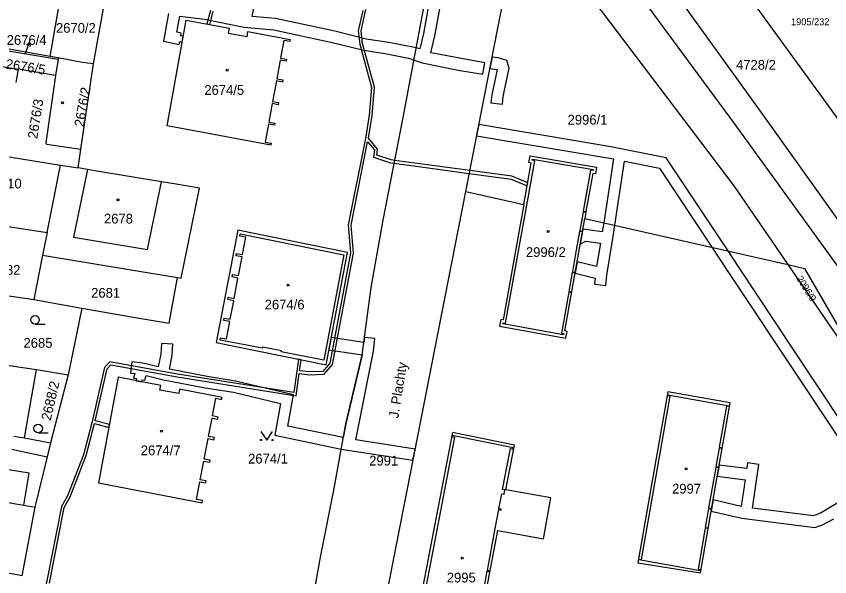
# Model space of a CAD drawing. Extents: x -756746 to -753363, y -1166406 to -1161727.
# Drawn here: x -755238.8 to -755096.9, y -1165184.7 to -1165086.9 of the extents above; entities that cross this region are included whole.
import ezdxf

# ---------------------------------------------------------------- set-up
doc = ezdxf.new("R2010")
doc.units = 0
for name, color, linetype in [('Hranice parcel', 7, 'Continuous'), ('Parcelní čísla', 7, 'Continuous'), ('Pop  PČ popisy', 7, 'Continuous'), ('Poz předměty', 7, 'Continuous'), ('Vnitřní kresba', 7, 'Continuous'), ('Věcná břemena k části', 7, 'Continuous'), ('Značky budov', 7, 'Continuous'), ('Značky kultur', 7, 'Continuous')]:
    doc.layers.add(name, color=color, linetype=linetype)

msp = doc.modelspace()

# ---------------------------------------------------------------- linework, layer by layer
at = {"layer": 'Hranice parcel'}
for p, q in [((-755160.42, -1165117.49), (-755150.8, -1165068.69)), ((-755225.33, -1165095.26), (-755222.94, -1165081.86)), ((-755232.91, -1165093.94), (-755242.08, -1165092.35)), ((-755241.62, -1165092.72), (-755231.52, -1165094.42)), ((-755231.49, -1165094.19), (-755232.91, -1165093.94)), ((-755231.49, -1165094.19), (-755231.52, -1165094.42)), ((-755242.1, -1165095.57), (-755238.48, -1165096.18)), ((-755231.52, -1165094.42), (-755231.95, -1165097.29)), ((-755227.53, -1165110.13), (-755225.33, -1165095.26)), ((-755238.48, -1165096.18), (-755238.88, -1165098.48)), ((-755231.95, -1165097.29), (-755238.48, -1165096.18)), ((-755228.02, -1165113.41), (-755227.53, -1165110.13)), ((-755233.44, -1165124.65), (-755231.1, -1165112.95)), ((-755231.1, -1165112.95), (-755228.02, -1165113.41)), ((-755179.62, -1165215.45), (-755160.42, -1165117.49)), ((-755160.42, -1165117.49), (-755150.27, -1165119.8)), ((-755139.46, -1165121.18), (-755139.65, -1165122.21)), ((-755140.68, -1165128.11), (-755139.65, -1165122.21)), ((-755139.65, -1165122.21), (-755104.24, -1165130.26)), ((-755246.05, -1165122.75), (-755233.44, -1165124.65)), ((-755233.44, -1165124.65), (-755234.22, -1165128.61)), ((-755234.22, -1165128.61), (-755235.77, -1165136.38)), ((-755234.22, -1165128.61), (-755210.71, -1165132.55)), ((-755104.24, -1165130.26), (-755087.72, -1165154.39)), ((-755242.45, -1165135.36), (-755235.77, -1165136.38)), ((-755227.37, -1165137.87), (-755229.77, -1165149.51)), ((-755242.09, -1165147.57), (-755235.29, -1165148.57)), ((-755237.41, -1165160.49), (-755235.29, -1165148.57)), ((-755235.29, -1165148.57), (-755229.77, -1165149.51)), ((-755229.77, -1165149.51), (-755232.82, -1165161.37)), ((-755239.26, -1165160.22), (-755237.41, -1165160.49)), ((-755237.41, -1165160.49), (-755232.82, -1165161.37)), ((-755237.49, -1165172.27), (-755235.61, -1165172.6))]:
    msp.add_line(p, q, dxfattribs=at)
for points in [[(-755195.18, -1165232.73), (-755194.72, -1165230.22), (-755190.08, -1165204.4), (-755187.88, -1165193.31), (-755185.72, -1165181.35), (-755183.4, -1165169.62), (-755181.35, -1165158.07), (-755178.5, -1165145.99), (-755176.9, -1165134.25), (-755174.82, -1165122.5), (-755171.34, -1165104.62), (-755169.11, -1165092.87), (-755166.91, -1165081.07), (-755164.91, -1165069.54), (-755163.98, -1165065.31), (-755179.46, -1165046.33)], [(-755128.64, -1165061.22), (-755109.28, -1165085.91), (-755070.16, -1165139.75), (-755029.65, -1165203.95), (-755020.68, -1165217.39)], [(-755143.12, -1165077.96), (-755139.65, -1165082.14), (-755113.63, -1165116.54), (-755104.24, -1165130.26)], [(-755071.5, -1165165.83), (-755094.76, -1165131.6), (-755113.5, -1165105.68), (-755130.36, -1165082.71), (-755132.91, -1165079.45)], [(-755232.91, -1165093.94), (-755230.59, -1165080.61), (-755222.94, -1165081.86)], [(-755191.09, -1165091.34), (-755192.15, -1165091.15), (-755192.71, -1165094.24), (-755191.66, -1165094.43), (-755191.73, -1165094.8), (-755192.79, -1165094.61), (-755193.37, -1165097.85), (-755192.33, -1165098.04), (-755192.39, -1165098.41), (-755193.45, -1165098.22), (-755194.1, -1165101.8), (-755193.06, -1165101.99), (-755193.12, -1165102.37), (-755194.18, -1165102.17), (-755194.77, -1165105.41), (-755193.72, -1165105.61), (-755193.78, -1165105.97), (-755194.83, -1165105.77), (-755195.41, -1165108.88), (-755194.35, -1165109.08), (-755194.43, -1165109.43), (-755212.52, -1165106.05), (-755209.2, -1165087.6), (-755201.69, -1165088.99), (-755201.86, -1165089.88), (-755198.56, -1165090.49), (-755198.4, -1165089.6), (-755191.02, -1165090.97), (-755191.09, -1165091.34)], [(-755225.33, -1165095.26), (-755227.34, -1165094.98), (-755231.49, -1165094.19)], [(-755231.95, -1165097.29), (-755233.69, -1165109), (-755233.54, -1165109.24), (-755227.53, -1165110.13)], [(-755249.11, -1165110.01), (-755248.72, -1165110.07), (-755231.1, -1165112.95)], [(-755150.27, -1165119.8), (-755148.97, -1165112.55), (-755149.4, -1165112.47), (-755149.19, -1165111.3), (-755137.58, -1165113.28)], [(-755210.71, -1165132.55), (-755210.08, -1165132.66), (-755206.88, -1165116.94), (-755210.94, -1165116.24), (-755213.46, -1165115.83), (-755224.74, -1165113.97), (-755226.41, -1165113.7), (-755228.02, -1165113.41)], [(-755137.58, -1165113.28), (-755137.79, -1165114.45), (-755138.22, -1165114.37), (-755139.43, -1165121.02), (-755139.46, -1165121.18)], [(-755150.27, -1165119.8), (-755151.42, -1165126.23), (-755153.87, -1165139.91), (-755154.3, -1165139.83), (-755154.52, -1165141), (-755142.92, -1165143.09)], [(-755200.17, -1165124.26), (-755203.92, -1165143.88), (-755184.78, -1165147.76), (-755181.05, -1165128.16), (-755200.17, -1165124.26)], [(-755142.92, -1165143.09), (-755142.71, -1165141.92), (-755143.14, -1165141.84), (-755140.68, -1165128.11)], [(-755104.24, -1165130.26), (-755101.31, -1165130.93), (-755087.72, -1165154.39)], [(-755227.37, -1165137.87), (-755218.06, -1165139.49), (-755212.14, -1165140.47), (-755210.71, -1165132.55)], [(-755235.77, -1165136.38), (-755230.93, -1165137.25), (-755227.37, -1165137.87)], [(-755207.36, -1165171.26), (-755206.78, -1165168.17), (-755205.74, -1165168.37), (-755205.68, -1165168), (-755206.71, -1165167.81), (-755206.1, -1165164.58), (-755205.07, -1165164.77), (-755204.99, -1165164.41), (-755206.02, -1165164.21), (-755205.35, -1165160.64), (-755204.33, -1165160.83), (-755204.25, -1165160.46), (-755205.28, -1165160.27), (-755204.67, -1165157.04), (-755203.64, -1165157.24), (-755203.57, -1165156.87), (-755204.59, -1165156.68), (-755204.02, -1165153.6), (-755202.99, -1165153.79), (-755202.92, -1165153.45), (-755210.33, -1165152.01), (-755210.48, -1165152.79), (-755213.77, -1165152.16), (-755213.62, -1165151.37), (-755221.03, -1165149.94), (-755224.5, -1165168.35), (-755206.4, -1165171.82), (-755206.33, -1165171.45), (-755207.36, -1165171.26)], [(-755125.15, -1165152.46), (-755127.78, -1165167.38), (-755130.41, -1165182.34), (-755119.46, -1165184.03), (-755116.89, -1165169.3), (-755114.29, -1165154.4), (-755125.15, -1165152.46)], [(-755160.8, -1165208.04), (-755159.55, -1165201.4), (-755151.54, -1165202.7), (-755150.29, -1165195.89), (-755158.19, -1165194.35), (-755154.79, -1165176.66), (-755146.86, -1165178.15), (-755145.57, -1165170.99), (-755153.44, -1165169.6), (-755151.91, -1165161.77), (-755162.74, -1165159.58), (-755165.57, -1165174.33), (-755169.05, -1165192.5), (-755171.87, -1165207.15), (-755165.18, -1165208.46)], [(-755232.82, -1165161.37), (-755233.42, -1165163.8), (-755235.61, -1165172.6)], [(-755255.14, -1165169.18), (-755251.05, -1165169.95), (-755248.2, -1165170.48), (-755242.64, -1165171.4), (-755241.26, -1165171.62), (-755237.49, -1165172.27)], [(-755235.61, -1165172.6), (-755237.84, -1165184.59), (-755238.67, -1165184.43)], [(-755238.67, -1165184.43), (-755243.01, -1165183.71), (-755248, -1165183.01), (-755253.35, -1165182.1), (-755259.87, -1165180.99)]]:
    msp.add_lwpolyline(points, dxfattribs=at)
at = {"layer": 'Pop  PČ popisy'}
for p, q in [((-755237.23, -1165093.35), (-755236.51, -1165091.47)), ((-755236.51, -1165091.47), (-755237.06, -1165091.98)), ((-755236.51, -1165091.47), (-755236.44, -1165092.22))]:
    msp.add_line(p, q, dxfattribs=at)
at = {"layer": 'Poz předměty'}
for p, q in [((-755108.7, -1165103.93), (-755146.57, -1165051.26)), ((-755089.86, -1165130.3), (-755108.7, -1165103.93))]:
    msp.add_line(p, q, dxfattribs=at)
at = {"layer": 'Vnitřní kresba'}
for p, q in [((-755149.78, -1165119.91), (-755148.38, -1165112.14)), ((-755148.81, -1165112.06), (-755148.78, -1165111.89)), ((-755148.38, -1165112.14), (-755148.81, -1165112.06)), ((-755148.78, -1165111.89), (-755138.17, -1165113.69)), ((-755226.41, -1165113.7), (-755228.82, -1165125.49)), ((-755138.63, -1165113.78), (-755139.92, -1165120.94)), ((-755138.2, -1165113.86), (-755138.63, -1165113.78)), ((-755138.17, -1165113.69), (-755138.2, -1165113.86)), ((-755215.93, -1165127.65), (-755213.46, -1165115.83)), ((-755150.93, -1165126.32), (-755149.78, -1165119.91)), ((-755139.94, -1165121.09), (-755140.12, -1165122.1)), ((-755139.46, -1165121.18), (-755139.94, -1165121.09)), ((-755139.92, -1165120.94), (-755139.43, -1165121.02)), ((-755140.12, -1165122.1), (-755140.53, -1165124.35)), ((-755228.82, -1165125.49), (-755215.93, -1165127.65)), ((-755199.83, -1165125.29), (-755199.75, -1165124.88)), ((-755198.8, -1165125.49), (-755199.83, -1165125.29)), ((-755199.75, -1165124.88), (-755181.68, -1165128.57)), ((-755199.36, -1165128.52), (-755198.8, -1165125.49)), ((-755140.55, -1165124.5), (-755141.18, -1165128.03)), ((-755140.12, -1165124.57), (-755140.55, -1165124.5)), ((-755140.53, -1165124.35), (-755140.1, -1165124.43)), ((-755140.1, -1165124.43), (-755140.12, -1165124.57)), ((-755153.47, -1165140.5), (-755150.93, -1165126.32)), ((-755200.48, -1165128.74), (-755200.4, -1165128.33)), ((-755200.4, -1165128.33), (-755199.36, -1165128.52)), ((-755141.18, -1165128.03), (-755141.81, -1165131.53)), ((-755199.44, -1165128.93), (-755200.48, -1165128.74)), ((-755200.06, -1165132.19), (-755199.44, -1165128.93)), ((-755181.68, -1165128.57), (-755185.16, -1165146.93)), ((-755201.17, -1165132.41), (-755201.09, -1165131.99)), ((-755200.14, -1165132.61), (-755201.17, -1165132.41)), ((-755201.09, -1165131.99), (-755200.06, -1165132.19)), ((-755141.84, -1165131.67), (-755142.43, -1165134.97)), ((-755141.4, -1165131.74), (-755141.84, -1165131.67)), ((-755141.81, -1165131.53), (-755141.38, -1165131.6)), ((-755141.38, -1165131.6), (-755141.4, -1165131.74)), ((-755200.81, -1165136.16), (-755200.14, -1165132.61)), ((-755142.45, -1165135.1), (-755143.73, -1165142.26)), ((-755142.02, -1165135.18), (-755142.45, -1165135.1)), ((-755142.43, -1165134.97), (-755142, -1165135.05)), ((-755142, -1165135.05), (-755142.02, -1165135.18)), ((-755201.92, -1165136.37), (-755201.84, -1165135.96)), ((-755200.89, -1165136.57), (-755201.92, -1165136.37)), ((-755201.84, -1165135.96), (-755200.81, -1165136.16)), ((-755201.49, -1165139.81), (-755200.89, -1165136.57)), ((-755202.61, -1165140.03), (-755202.53, -1165139.62)), ((-755202.53, -1165139.62), (-755201.49, -1165139.81)), ((-755201.57, -1165140.22), (-755202.61, -1165140.03)), ((-755202.14, -1165143.25), (-755201.57, -1165140.22)), ((-755153.93, -1165140.59), (-755153.89, -1165140.42)), ((-755143.33, -1165142.5), (-755153.93, -1165140.59)), ((-755153.89, -1165140.42), (-755153.47, -1165140.5)), ((-755143.73, -1165142.26), (-755143.3, -1165142.33)), ((-755143.3, -1165142.33), (-755143.33, -1165142.5)), ((-755203.25, -1165143.47), (-755203.18, -1165143.06)), ((-755195.87, -1165144.88), (-755203.25, -1165143.47)), ((-755203.18, -1165143.06), (-755202.14, -1165143.25)), ((-755195.84, -1165144.69), (-755195.87, -1165144.88)), ((-755192.55, -1165145.32), (-755195.84, -1165144.69)), ((-755192.59, -1165145.51), (-755192.55, -1165145.32)), ((-755185.16, -1165146.93), (-755192.59, -1165145.51)), ((-755127.25, -1165167.47), (-755124.75, -1165153.23)), ((-755125.18, -1165153.15), (-755125.15, -1165152.97)), ((-755124.75, -1165153.23), (-755125.18, -1165153.15)), ((-755125.15, -1165152.97), (-755114.47, -1165154.89)), ((-755114.93, -1165154.99), (-755116.18, -1165162.15)), ((-755114.5, -1165155.06), (-755114.93, -1165154.99)), ((-755114.47, -1165154.89), (-755114.5, -1165155.06)), ((-755162.36, -1165160.37), (-755165.06, -1165174.43)), ((-755162.76, -1165160.11), (-755162.79, -1165160.29)), ((-755162.79, -1165160.29), (-755162.36, -1165160.37)), ((-755152.14, -1165162.27), (-755162.76, -1165160.11)), ((-755153.97, -1165169.5), (-755152.62, -1165162.36)), ((-755152.62, -1165162.36), (-755152.17, -1165162.45)), ((-755152.17, -1165162.45), (-755152.14, -1165162.27)), ((-755116.2, -1165162.28), (-755116.77, -1165165.52)), ((-755115.77, -1165162.36), (-755116.2, -1165162.28)), ((-755116.18, -1165162.15), (-755115.75, -1165162.22)), ((-755115.75, -1165162.22), (-755115.77, -1165162.36)), ((-755239.57, -1165162.49), (-755233.42, -1165163.8)), ((-755236.58, -1165166.69), (-755240.2, -1165166.11)), ((-755116.79, -1165165.66), (-755117.41, -1165169.21)), ((-755116.36, -1165165.73), (-755116.79, -1165165.66)), ((-755116.77, -1165165.52), (-755116.34, -1165165.59)), ((-755116.34, -1165165.59), (-755116.36, -1165165.73)), ((-755237.49, -1165172.27), (-755236.58, -1165166.69)), ((-755129.76, -1165181.72), (-755127.25, -1165167.47)), ((-755153.56, -1165169.57), (-755153.97, -1165169.5)), ((-755117.41, -1165169.21), (-755118.03, -1165172.74)), ((-755154.61, -1165172.89), (-755154.11, -1165170.25)), ((-755154.11, -1165170.25), (-755153.7, -1165170.33)), ((-755153.7, -1165170.33), (-755153.56, -1165169.57)), ((-755155.26, -1165176.31), (-755154.63, -1165173.02)), ((-755154.63, -1165173.02), (-755154.22, -1165173.1)), ((-755154.2, -1165172.97), (-755154.61, -1165172.89)), ((-755154.22, -1165173.1), (-755154.2, -1165172.97)), ((-755118.05, -1165172.88), (-755118.62, -1165176.12)), ((-755117.62, -1165172.96), (-755118.05, -1165172.88)), ((-755118.03, -1165172.74), (-755117.6, -1165172.81)), ((-755117.6, -1165172.81), (-755117.62, -1165172.96)), ((-755165.06, -1165174.43), (-755168.54, -1165192.59)), ((-755156.64, -1165183.66), (-755155.26, -1165176.31)), ((-755118.64, -1165176.27), (-755119.89, -1165183.43)), ((-755118.21, -1165176.34), (-755118.64, -1165176.27)), ((-755118.62, -1165176.12), (-755118.18, -1165176.19)), ((-755118.18, -1165176.19), (-755118.21, -1165176.34)), ((-755130.22, -1165181.81), (-755130.19, -1165181.65)), ((-755119.49, -1165183.68), (-755130.22, -1165181.81)), ((-755130.19, -1165181.65), (-755129.76, -1165181.72)), ((-755156.21, -1165183.74), (-755156.64, -1165183.66)), ((-755119.89, -1165183.43), (-755119.46, -1165183.51)), ((-755119.46, -1165183.51), (-755119.49, -1165183.68)), ((-755157.28, -1165187.03), (-755156.67, -1165183.79)), ((-755156.67, -1165183.79), (-755156.24, -1165183.87)), ((-755156.24, -1165183.87), (-755156.21, -1165183.74))]:
    msp.add_line(p, q, dxfattribs=at)
at = {"layer": 'Věcná břemena k části'}
for points in [[(-755166.94, -1165085.41), (-755167.77, -1165089.94), (-755168.4, -1165092.6), (-755169.04, -1165092.47), (-755173.82, -1165091.53), (-755177.78, -1165090.92), (-755183.24, -1165089.55), (-755193.59, -1165087.31), (-755197.66, -1165086.98), (-755194.2, -1165069.63)], [(-755212.24, -1165086.44), (-755213.13, -1165091.29), (-755210.39, -1165091.85), (-755210.3, -1165091.36), (-755209.89, -1165091.44), (-755209.71, -1165090.45), (-755210.12, -1165090.38), (-755210.03, -1165089.89), (-755210.81, -1165089.73), (-755210.3, -1165086.91), (-755205.99, -1165087.45), (-755199.06, -1165088.87), (-755193.89, -1165089.29), (-755183.7, -1165091.49), (-755178.18, -1165092.88), (-755174.16, -1165093.51), (-755170.38, -1165094.25), (-755169.43, -1165094.58), (-755167.99, -1165095.09), (-755161.75, -1165096.33), (-755157.44, -1165097.02), (-755157.09, -1165095.05), (-755166.52, -1165093.34), (-755165.81, -1165090.34), (-755164.48, -1165083.04)], [(-755149.69, -1165116.54), (-755149.59, -1165116.03), (-755152.38, -1165114.86), (-755159.71, -1165113.86), (-755172.79, -1165112.09), (-755173.42, -1165112), (-755175.94, -1165111.2), (-755175.82, -1165110.11), (-755177.4, -1165108.23), (-755176.75, -1165104.25), (-755176.34, -1165099.34), (-755178.42, -1165091.7), (-755178.67, -1165089.51), (-755177.82, -1165085.77)], [(-755178.37, -1165085.93), (-755179.17, -1165089.49), (-755178.91, -1165091.8), (-755176.85, -1165099.39), (-755177.25, -1165104.19), (-755177.91, -1165108.26), (-755180.92, -1165123.36), (-755180.49, -1165128.27), (-755184.13, -1165147.49), (-755185.32, -1165148.91), (-755187.58, -1165149), (-755189.39, -1165148.79), (-755189.12, -1165146.88), (-755189.61, -1165146.78), (-755190.42, -1165152.57), (-755210.7, -1165149.37), (-755222.5, -1165147.21), (-755223.44, -1165148.2)], [(-755204.95, -1165085.94), (-755205.57, -1165088.27), (-755205.08, -1165088.36), (-755204.46, -1165086.05)], [(-755158.12, -1165105.81), (-755158.51, -1165107.78), (-755134.66, -1165111.83), (-755136.34, -1165122.96), (-755136.58, -1165124.56), (-755139.98, -1165124.11), (-755140.44, -1165126.71), (-755139.48, -1165126.19), (-755136.89, -1165126.53), (-755137.58, -1165130.63), (-755140.98, -1165129.79), (-755141.33, -1165131.75), (-755137.85, -1165132.62), (-755137.97, -1165133.7), (-755135.99, -1165133.92), (-755135.79, -1165132.13), (-755134.78, -1165126.08), (-755134.38, -1165123.41), (-755132.69, -1165112.24), (-755126.63, -1165113.44), (-755117.47, -1165127.25), (-755114.43, -1165131.83), (-755101.61, -1165151.15), (-755090.03, -1165168.57), (-755098.5, -1165173.67), (-755099.72, -1165174.11), (-755110.39, -1165172.76), (-755109.28, -1165165.15), (-755111.26, -1165164.86), (-755111.4, -1165165.84), (-755116.18, -1165165.24), (-755116.53, -1165167.21), (-755111.69, -1165167.82), (-755112.36, -1165172.47), (-755117.24, -1165171.33), (-755117.59, -1165173.29), (-755112.27, -1165174.54), (-755099.49, -1165176.15), (-755098.16, -1165175.66), (-755096.19, -1165174.62)], [(-755051.31, -1165235.98), (-755056.2, -1165226.18), (-755068.76, -1165204.62), (-755071.9, -1165199.03), (-755075.13, -1165188.62), (-755087.62, -1165168.58), (-755099.95, -1165150.05), (-755112.77, -1165130.73), (-755114.65, -1165127.89), (-755125.43, -1165111.64), (-755135.1, -1165109.72), (-755158.12, -1165105.81)], [(-755233.03, -1165185.88), (-755230.45, -1165172.68), (-755229.41, -1165170.82), (-755226.62, -1165163.6), (-755225.17, -1165158.01), (-755222.68, -1165158.67), (-755222.58, -1165158.18), (-755225.06, -1165157.53), (-755222.99, -1165148.45), (-755222.32, -1165147.75), (-755210.78, -1165149.86), (-755189.99, -1165153.15), (-755189.46, -1165149.28), (-755187.6, -1165149.51), (-755185.08, -1165149.4), (-755183.66, -1165147.71), (-755179.99, -1165128.3), (-755180.42, -1165123.38), (-755177.52, -1165108.87), (-755176.34, -1165110.27), (-755176.48, -1165111.55), (-755173.53, -1165112.49), (-755172.89, -1165112.58), (-755159.8, -1165114.36), (-755152.51, -1165115.35), (-755149.69, -1165116.54)], [(-755223.44, -1165148.2), (-755225.6, -1165157.65), (-755227.1, -1165163.45), (-755229.86, -1165170.61), (-755230.93, -1165172.5), (-755233.52, -1165185.76), (-755236.33, -1165195.43), (-755237.58, -1165204.98), (-755238.14, -1165208.26), (-755240.89, -1165209.44)]]:
    msp.add_lwpolyline(points, dxfattribs=at)
for points in [[(-755156.19, -1165096.04), (-755154.91, -1165096.21), (-755155.86, -1165100.65), (-755156.01, -1165102.07), (-755154.02, -1165102.28), (-755153.88, -1165100.94), (-755152.83, -1165096), (-755153.26, -1165094.64), (-755154.76, -1165094.22), (-755155.81, -1165094.08)], [(-755213.5, -1165144.06), (-755213.59, -1165145.88), (-755214.06, -1165148.1), (-755216.74, -1165147.45), (-755218.66, -1165147.21), (-755218.92, -1165149.19), (-755218.16, -1165149.29), (-755218.34, -1165150.07), (-755217.85, -1165150.16), (-755217.93, -1165150.54), (-755216.94, -1165150.73), (-755216.87, -1165150.35), (-755216.38, -1165150.45), (-755216.18, -1165149.64), (-755213.12, -1165150.38), (-755205.85, -1165151.8), (-755200.93, -1165152.56), (-755192.73, -1165154.49), (-755193.74, -1165160.06), (-755182.13, -1165162.47), (-755169.62, -1165164.42), (-755169.23, -1165162.46), (-755179.59, -1165160.84), (-755176.51, -1165145.4), (-755176.25, -1165143.19), (-755178.09, -1165142.97), (-755178.21, -1165143.85), (-755183.88, -1165143.01), (-755184.28, -1165145.12), (-755178.5, -1165145.99), (-755181.35, -1165158.07), (-755181.77, -1165160.45), (-755191.42, -1165158.48), (-755190.43, -1165152.97), (-755200.55, -1165150.6), (-755205.51, -1165149.82), (-755212.11, -1165148.54), (-755211.61, -1165146.14), (-755211.51, -1165144.16)]]:
    msp.add_lwpolyline(points, close=True, dxfattribs=at)
at = {"layer": 'Značky budov'}
for centre in [(-755202.03, -1165096.34), (-755230.74, -1165102.02), (-755221.07, -1165118.95), (-755146.03, -1165124.51), (-755191.4, -1165133.85), (-755213.47, -1165159.32), (-755121.97, -1165165.92), (-755161.04, -1165181.5)]:
    msp.add_circle(centre, 0.175, dxfattribs=at)
at = {"layer": 'Značky kultur'}
for p, q in [((-755235.55, -1165140.65), (-755233.8, -1165140.65)), ((-755235.02, -1165159.64), (-755233.27, -1165159.64))]:
    msp.add_line(p, q, dxfattribs=at)
msp.add_lwpolyline([(-755196.13, -1165159.38), (-755195.13, -1165160.88), (-755194.13, -1165159.38)], dxfattribs=at)
for centre, radius in [((-755235.55, -1165139.9), 0.75), ((-755235.02, -1165158.89), 0.75), ((-755196.13, -1165160.88), 0.1), ((-755194.13, -1165160.88), 0.1)]:
    msp.add_circle(centre, radius, dxfattribs=at)

# ---------------------------------------------------------------- texts
at = {"layer": 'Parcelní čísla'}
for s, height, p in [('2670/2', 1.7, (-755231.9, -1165089.82)), ('1905/232', 1.2, (-755103.66, -1165088.5)), ('2676/4', 1.7, (-755240.49, -1165091.93)), ('4728/2', 1.7, (-755113.26, -1165096.26)), ('2674/5', 1.7, (-755206.02, -1165100.65)), ('2996/1', 1.7, (-755142.64, -1165105.84)), ('2676/10', 1.7, (-755246.09, -1165116.98)), ('2678', 1.7, (-755223.52, -1165123.1)), ('2996/2', 1.7, (-755149.91, -1165128.94)), ('2682', 1.7, (-755243.15, -1165132.05)), ('2681', 1.7, (-755225.76, -1165136.05)), ('2674/6', 1.7, (-755195.48, -1165138.09)), ('2685', 1.7, (-755237.56, -1165144.78)), ('2674/7', 1.7, (-755217.1, -1165163.53)), ('2674/1', 1.7, (-755198.38, -1165164.98)), ('2991', 1.7, (-755177.25, -1165165.33)), ('2997', 1.7, (-755124.42, -1165170.22)), ('2995', 1.7, (-755163.72, -1165185.73))]:
    msp.add_text(s, height=height, dxfattribs=at).set_placement(p)
for s, height, rotation, p in [('2676/5', 1.7, 351, (-755240.75, -1165096.05)), ('2676/2', 1.7, 80, (-755227.05, -1165106.33)), ('2676/3', 1.7, 81, (-755235.16, -1165108.39)), ('2096/9', 1.2, 302, (-755102.77, -1165132.67)), ('2688/2', 1.7, 77, (-755232.83, -1165157.6))]:
    msp.add_text(s, height=height, rotation=rotation, dxfattribs=at).set_placement(p)
at = {"layer": 'Pop  PČ popisy'}
msp.add_text('J. Plachty', height=1.7, rotation=81, dxfattribs=at).set_placement((-755172.18, -1165157.17))

doc.saveas('drawing.dxf')
